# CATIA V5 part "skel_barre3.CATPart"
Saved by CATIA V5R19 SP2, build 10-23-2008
Part number: skel_barre5
Bounding box of the stored display mesh (mm): x 0 to 20, y 18 to 27.955, z 0 to 0.952
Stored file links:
  E:\TRAVAIL\IAO\skel_barre3.CATPart
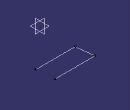
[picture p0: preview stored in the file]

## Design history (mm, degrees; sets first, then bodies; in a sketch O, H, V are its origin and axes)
Body1 (main body)
  Point1 "Point.C": stored without definition
  Point2 "Point.B": stored without definition
  Line1 "barre_5": type PtPt, FirstPoint Point1, SecondPoint Point2
  Plane1 "Plan_ref": stored without definition
  Point3 "Point.B": stored without definition
  Line2 "axe_pivot_barre2_barre5": type Normal, RefPoint Point3, RefSkin Plane1, Start 0, End 20
  Plane2 "Plan_ref": stored without definition
  Point4 "Point.C": stored without definition
  Line3 "axe_pivot_barre5_bati": type Normal, RefPoint Point4, RefSkin Plane2, Start 0, End 20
